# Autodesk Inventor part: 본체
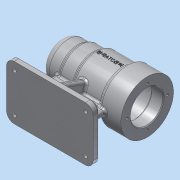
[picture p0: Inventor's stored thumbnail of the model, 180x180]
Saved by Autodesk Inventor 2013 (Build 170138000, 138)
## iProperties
Created: 2016-06
Part Number: 본체
Material: 알루미늄 6061
Document SubType Name: Modeling
Designer: dgall
Density: 2.71 g/cm^3
Mass: 673.897 g
Surface Area: 647.222 cm^2
Volume: 248.67 cm^3
Author: dgall
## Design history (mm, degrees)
sketch "스케치1"
  geometry: L1 (-56, 0)-(56, 0); L2 (-56, 0)-(-56, 25); L3 (-56, 25)-(-31, 25); L4 (-31, 25)-(-31, 27); L5 (-31, 27)-(-11, 27); L6 (-11, 27)-(-11, 30); L7 (-11, 30)-(28, 30); L8 (28, 34)-(56, 34); L9 (56, 34)-(56, 21); L10 (-50, 0)-(-50, 10.5); L11 (-50, 10.5)-(-47, 10.5); L12 (-47, 10.5)-(-47, 16); L13 (-47, 16)-(-43, 16); L14 (-43, 16)-(-43, 17.5); L15 (-43, 17.5)-(-25, 17.5); L16 (-25, 17.5)-(-25, 21); L17 (-25, 21)-(-13, 21); L18 (-13, 21)-(-13, 24); L19 (-13, 24)-(41, 24); L20 (41, 24)-(41, 21); L21 (41, 21)-(56, 21); L22 (-56, 0)-(-50, 0); L23 (28, 34)-(28, 30); 2 further points
  constraints: 46 end point, 16 parallel, 4 perpendicular, 1 coincident, 1 collinear, 1 horizontal, 1 midpoint, 1 point on line, 1 vertical, 1 vertical alignment
  dimensions: "d0" = 112 distance of L1.start L1.end; "d3" = 21 diameter of L11 L1; "d4" = 32 diameter of L13 L1; "d5" = 35 diameter of L15 L1; "d6" = 42 diameter of L17 L1; "d7" = 48 diameter of L19 L1; "d8" = 42 diameter of L21 L1; "d9" = 50 diameter of L3 L1; "d10" = 54 diameter of L5 L1; "d11" = 60 diameter of L7 L1; "d12" = 68 diameter of L8 L1; "d13" = 3 distance of L10.end L11.end; "d14" = 4 distance of L12.end L13.end; "d15" = 18 distance of L14.end L15.end; "d16" = 12 distance of L16.end L17.end; "d17" = 54 distance of L18.end L19.end; "d18" = 15 distance of L9.end L20.end; "d19" = 25 distance between parallel lines of L4 L2; "d20" = 45 distance between parallel lines of L6 L2; "d22" = 84 distance between parallel lines of L23 L2
revolve "회전1" sketch "스케치1" stored, may be unused: angle "d23" = 90 deg
fillet "모깎기1" dims "d24" = 10
fillet "모깎기2" dims "d25" = 3
fillet "모깎기3" dims "d26" = 0.3
chamfer "모따기1" distance "d27" = 1; stored, may be unused: second distance "d28" = 2, angle "d29" = 45 deg
sketch "스케치2" dims "d30" = 52
  geometry: C1 r 34 at (0, 0) reference; C2 r 22 at (0, 0) reference; 2 further points
  constraints: 2 vertical alignment, 1 coincident, 2 other
hole "구멍1" sketch "스케치2" at (0, 26) diameter "d31" = 3.242; stored, may be unused: countersink angle "d35" = 90 deg, drill point angle "d37" = 118 deg; dims "d32" = 8, "d33" = 4, "d34" = 2, "d36" = 11
fillet "모깎기4" dims "d41" = 3
node "작업 평면1"
sketch "스케치3"
  geometry: L1 (46, -35)-(-46, -35); L2 (-56, -25)-(-56, 25); L3 (-46, 35)-(46, 35); L4 (56, 25)-(56, -25); L5 (-36, 4)-(36, 4); L6 (36, 4)-(36, -4); L7 (36, -4)-(-36, -4); L8 (-36, -4)-(-36, 4); A1 r 10 centre (46, -25) between (46, -35) and (56, -25); A2 r 10 centre (-46, 25) between (-46, 35) and (-56, 25); A3 r 10 centre (-46, -25) between (-56, -25) and (-46, -35); A4 r 10 centre (46, 25) between (56, 25) and (46, 35); 8 further points
  constraints: 16 end point, 8 point on circle, 8 tangent, 6 point on line, 4 centre point, 4 midpoint, 4 parallel, 3 equal radius, 2 horizontal, 2 horizontal alignment, 2 perpendicular, 2 vertical alignment
  dimensions: "d43" = 112 distance of point (56, -35) point (-56, -35); "d45" = 70 distance of point (-56, -35) point (-56, 35); "d46" = 10 radius of A1; "d47" = 8 distance of L7.end L5.start; "d48" = 20 distance between parallel lines of L6 L4
extrude "돌출1" join sketch "스케치3" distance "d49" = 10; taper "d50" = 0 deg
extrude "돌출2" join sketch "스케치3" stored distance "d51" = 10; taper "d52" = 0 deg
chamfer "모따기2" distance "d53" = 4; stored, may be unused: second distance "d54" = 2, angle "d55" = 45 deg
hole "구멍2" diameter "d58" = 5; stored, may be unused: countersink angle "d62" = 90 deg, drill point angle "d64" = 118 deg; dims "d56" = 10, "d57" = 10, "d59" = 8, "d60" = 9, "d61" = 4, "d63" = 11
sketch "스케치6"
  geometry: L1 (-60, 25)-(-60, -25) reference; L2 (-60, 29.5)-(-60, 20.5) reference; L3 (-60, 28)-(-27.62, 16.214); L4 (-70, 35)-(-64, 35) reference; A1 r 30 centre (0, 0) between (-29.732, -4) and (-29.732, 4) reference; 1 further point
  constraints: 2 end point, 1 point on line
  dimensions: "d65" = 7 distance from line of L3.start L4; "d66" = 110 deg angle of L2 L3
feature "리브1" sketch "스케치6" dims "d67" = 1, "d68" = 8, "d69" = 0, "d70" = 0, "d71" = 1, "d72" = 1
fillet "모깎기5" dims "d73" = 3
fillet "모깎기6" dims "d74" = 3
node "작업 평면3"
sketch "스케치7"
  geometry: L1 (-20.5, 10)-(19.5, 10); L2 (19.5, 10)-(19.5, -10); L3 (19.5, -10)-(-20.5, -10); L4 (-20.5, -10)-(-20.5, 10); L5 (47.5, -34)-(47.5, 34) reference; 5 further points
  constraints: 4 midpoint, 2 horizontal alignment, 1 vertical alignment, 2 other
  dimensions: "d76" = 40 distance of L1.start L1.end; "d78" = 20 distance of L1.end L2.end; "d79" = 48 distance from line of point (-0.5, 10) L5
feature "엠보싱1" sketch "스케치7" dims "d0" = 112, "d3" = 21, "d4" = 32, "d5" = 35, "d6" = 42, "d7" = 48, "d8" = 42, "d9" = 50, "d10" = 54, "d11" = 60, "d12" = 68, "d13" = 3, "d14" = 4, "d15" = 18, "d16" = 12, "d17" = 54, "d18" = 15, "d19" = 25, "d20" = 45, "d22" = 84, "d80" = 0.5, "d81" = 0
node "솔리드1"
pattern_circular "원형 패턴1" dims angle "d39" = 360 deg
mirror "대칭1"
mirror "대칭3"
mirror "대칭4"
